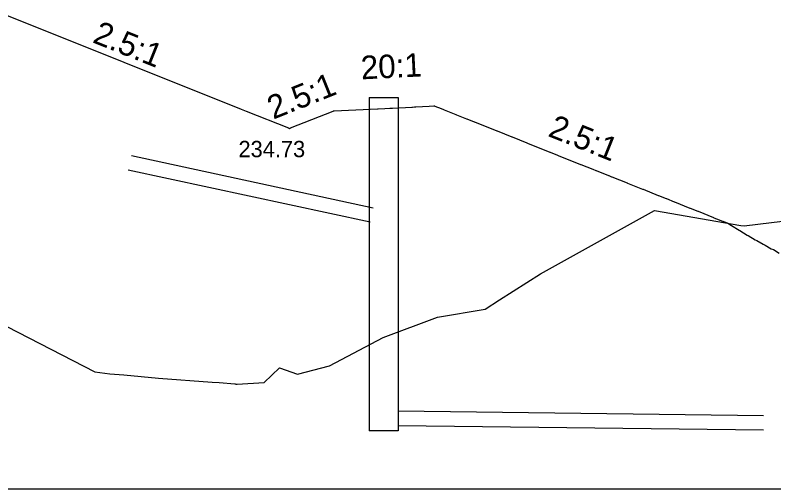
# Model space of a CAD drawing. Extents: x -26 to 1629, y -25 to 9635.
# Drawn here: x 312.2 to 416.8, y 6000 to 6065.4 of the extents above; entities that cross this region are included whole.
import ezdxf

# ---------------------------------------------------------------- set-up
doc = ezdxf.new("R2010")
doc.units = 0
for name, color, linetype in [('DTM CONTOURS_MAJOR', 7, 'Continuous'), ('DTM_X_GROUND', 7, 'Continuous'), ('XS_CELL', 7, 'Continuous'), ('XS_P_DRAINAGE', 7, 'Continuous'), ('XS_P_GROUND', 7, 'Continuous'), ('XS_P_TX_DCH', 7, 'Continuous'), ('XS_P_TX_FS_BS', 7, 'Continuous')]:
    doc.layers.add(name, color=color, linetype=linetype)

msp = doc.modelspace()

# ---------------------------------------------------------------- linework, layer by layer
at = {"layer": 'DTM_X_GROUND'}
msp.add_lwpolyline([(311, 6022.42), (323.13, 6016.13), (325.2, 6015.88), (327.14, 6015.73), (331.91, 6015.25), (339.31, 6014.7), (340.29, 6014.69), (342.44, 6014.47), (342.52, 6014.47), (342.6, 6014.46), (342.77, 6014.46), (346.5, 6014.67), (348.62, 6016.71), (351.08, 6015.83), (355.53, 6016.95), (362.94, 6020.87), (370.42, 6023.69), (376.97, 6024.79), (378.98, 6026.07), (384.63, 6029.68), (400.37, 6038.39), (412.28, 6036.32), (412.71, 6036.31), (434.26, 6038.93)], dxfattribs=at)
at = {"layer": 'XS_CELL'}
msp.add_line((100, 6000), (550, 6000), dxfattribs=at)
at = {"layer": 'XS_P_DRAINAGE'}
for p, q in [((361, 6054.01), (361, 6022)), ((361, 6054.01), (365, 6054.01)), ((361, 6054.01), (361, 6008.01)), ((365, 6054.01), (365, 6022)), ((365, 6054.01), (365, 6008.01)), ((328.18, 6045.97), (361.56, 6038.77)), ((327.76, 6044.01), (361.14, 6036.82)), ((365, 6010.75), (415.4, 6010.12)), ((365, 6008.75), (415.4, 6008.12)), ((365, 6008.01), (361, 6008.01))]:
    msp.add_line(p, q, dxfattribs=at)
at = {"layer": 'XS_P_GROUND'}
for points in [[(310.95, 6065.35), (343.33, 6052.4), (344, 6052.13), (349.85, 6049.79), (350, 6049.73), (350.15, 6049.79), (356, 6052.13), (356.08, 6052.14), (356.17, 6052.14), (362.16, 6052.44), (362.24, 6052.45), (363.17, 6052.49), (363.86, 6052.53), (364.1, 6052.54), (364.18, 6052.54), (364.19, 6052.54), (366.89, 6052.68), (366.96, 6052.68), (367.24, 6052.7), (367.24, 6052.7), (367.42, 6052.7), (369.28, 6052.8), (369.92, 6052.83), (370, 6052.83), (370.04, 6052.82), (370.93, 6052.46), (371.23, 6052.34), (371.33, 6052.3), (372.94, 6051.66), (372.95, 6051.66), (373.04, 6051.62), (374.43, 6051.06), (374.45, 6051.05), (375.46, 6050.65), (375.54, 6050.62), (378.58, 6049.4), (378.63, 6049.38), (380.66, 6048.57), (380.72, 6048.55), (382.76, 6047.73), (382.84, 6047.7), (385.91, 6046.47), (385.94, 6046.46), (386.97, 6046.05), (387.05, 6046.01), (390.15, 6044.77), (390.19, 6044.76), (391.84, 6044.1), (391.85, 6044.09), (392.28, 6043.92), (392.32, 6043.9), (394.02, 6043.22), (394.03, 6043.22), (394.42, 6043.07), (394.47, 6043.05), (396.56, 6042.21), (396.61, 6042.19), (398.71, 6041.35), (398.77, 6041.33), (400.88, 6040.48), (400.9, 6040.47), (401.96, 6040.05), (401.99, 6040.04), (403.05, 6039.62), (403.1, 6039.59), (405.22, 6038.74), (405.25, 6038.73), (406.31, 6038.31), (406.37, 6038.29), (408.5, 6037.43), (408.56, 6037.41), (408.92, 6037.27), (409.72, 6036.95), (409.76, 6036.93), (409.77, 6036.92), (409.79, 6036.92), (409.8, 6036.91), (409.89, 6036.88), (409.91, 6036.87), (409.94, 6036.86), (409.95, 6036.85), (409.97, 6036.85), (409.97, 6036.84), (410.02, 6036.83), (410.03, 6036.82), (410.07, 6036.81), (410.08, 6036.8), (410.12, 6036.78), (410.14, 6036.78), (410.18, 6036.76), (410.19, 6036.76), (410.25, 6036.73), (410.27, 6036.72), (410.31, 6036.71), (410.33, 6036.7), (410.34, 6036.7), (410.36, 6036.69), (410.39, 6036.68), (410.4, 6036.67), (410.45, 6036.65), (410.47, 6036.64), (410.48, 6036.64)], [(410.48, 6036.64), (410.96, 6036.34), (410.98, 6036.34), (412.05, 6035.67), (412.13, 6035.63), (413.15, 6035.01), (413.29, 6034.95), (414.25, 6034.37), (414.45, 6034.28), (415.35, 6033.74), (415.61, 6033.63), (416.46, 6033.13), (416.76, 6033), (417.56, 6032.53)]]:
    msp.add_lwpolyline(points, dxfattribs=at)

# ---------------------------------------------------------------- texts
at = {"layer": 'DTM CONTOURS_MAJOR'}
for p in [(369.96, 6052.77), (343.96, 6052.07), (355.96, 6052.07), (349.96, 6049.67), (410.44, 6036.58)]:
    msp.add_text('X', height=0.12, dxfattribs=at).set_placement(p)
at = {"layer": 'XS_P_TX_DCH'}
msp.add_text('234.73', height=2.25, dxfattribs=at).set_placement((342.96, 6045.76))
at = {"layer": 'XS_P_TX_FS_BS'}
for s, rotation, p in [('2.5:1', 338.1986, (322.7, 6061.64)), ('20:1', 2.8624, (359.91, 6056.49)), ('2.5:1', 21.8014, (347.76, 6050.93)), ('2.5:1', 338.1979, (385.52, 6048.71))]:
    msp.add_text(s, height=3.24, rotation=rotation, dxfattribs=at).set_placement(p)

doc.saveas('drawing.dxf')
